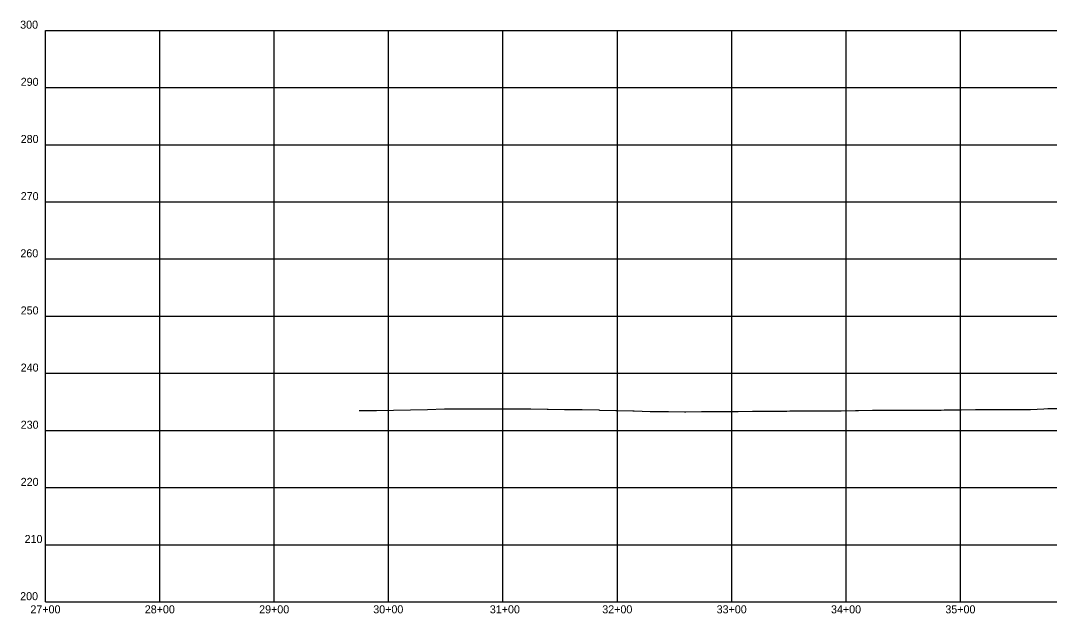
# Model space of a CAD drawing. Extents: x 976639 to 985448, y 1524031 to 1526806.
# Drawn here: x 982604 to 983504, y 1524031 to 1524550 of the extents above; entities that cross this region are included whole.
import ezdxf

# ---------------------------------------------------------------- set-up
doc = ezdxf.new("R2010")
doc.units = 0
for name, color, linetype in [('Default', 7, 'Continuous'), ('R_Axis', 7, 'Continuous'), ('R_Axis Annot', 7, 'Continuous'), ('R_Grid', 7, 'Continuous')]:
    doc.layers.add(name, color=color, linetype=linetype)

msp = doc.modelspace()

# ---------------------------------------------------------------- linework, layer by layer
at = {"layer": 'Default'}
msp.add_lwpolyline([(982900.37, 1524208.73), (982915.54, 1524208.85), (982930.35, 1524209.11), (982945.22, 1524209.57), (982960.19, 1524209.73), (982960.19, 1524209.73), (982960.19, 1524209.73), (982960.23, 1524209.73), (982974.94, 1524210.38), (982975.68, 1524210.39), (982990.12, 1524210.36), (982990.33, 1524210.36), (983000.59, 1524210.4), (983005.17, 1524210.4), (983005.26, 1524210.4), (983020.12, 1524210.4), (983020.15, 1524210.4), (983021.68, 1524210.4), (983035.01, 1524210.31), (983035.34, 1524210.3), (983049.93, 1524210.19), (983050.5, 1524210.18), (983064.85, 1524210.16), (983065.63, 1524210.14), (983080.02, 1524209.8), (983080.33, 1524209.8), (983095.02, 1524209.7), (983095.32, 1524209.69), (983109.87, 1524209.31), (983110.62, 1524209.3), (983124.88, 1524209.01), (983125.58, 1524209), (983139.79, 1524208.61), (983140.76, 1524208.6), (983154.91, 1524208.01), (983155.54, 1524208.01), (983169.77, 1524207.9), (983170.82, 1524207.9), (983184.76, 1524207.75), (983186.08, 1524207.75), (983199.67, 1524207.89), (983201.25, 1524207.88), (983214.53, 1524207.96), (983216.53, 1524207.94), (983229.44, 1524208.03), (983231.7, 1524208.01), (983244.43, 1524208.23), (983246.72, 1524208.22), (983259.4, 1524208.28), (983261.79, 1524208.31), (983274.37, 1524208.4), (983276.85, 1524208.43), (983289.2, 1524208.43), (983292.15, 1524208.48), (983304.3, 1524208.46), (983306.95, 1524208.5), (983319.35, 1524208.69), (983321.89, 1524208.69), (983334.27, 1524208.94), (983337.06, 1524209), (983349.17, 1524209.15), (983352.35, 1524209.17), (983364.07, 1524209.14), (983367.52, 1524209.13), (983379.1, 1524209.15), (983382.46, 1524209.13), (983394.15, 1524209.26), (983397.39, 1524209.29), (983409.35, 1524209.3), (983411.97, 1524209.33), (983424.42, 1524209.46), (983426.87, 1524209.5), (983439.3, 1524209.68), (983442.1, 1524209.77), (983454.06, 1524209.74), (983457.54, 1524209.86), (983469.07, 1524209.62), (983472.52, 1524209.68), (983484.22, 1524209.7), (983487.31, 1524209.73), (983499.1, 1524210.4), (983502.53, 1524210.49), (983514.16, 1524210.75)], dxfattribs=at)
at = {"layer": 'R_Axis'}
for q in [(982626.18, 1524541.42), (985426.18, 1524041.42)]:
    msp.add_line((982626.18, 1524041.42), q, dxfattribs=at)
at = {"layer": 'R_Grid'}
for p, q in [((982626.18, 1524541.42), (985426.18, 1524541.42)), ((982626.18, 1524541.42), (985426.18, 1524541.42)), ((982726.18, 1524041.42), (982726.18, 1524541.42)), ((982826.18, 1524041.42), (982826.18, 1524541.42)), ((982926.18, 1524041.42), (982926.18, 1524541.42)), ((983026.18, 1524041.42), (983026.18, 1524541.42)), ((983126.18, 1524041.42), (983126.18, 1524541.42)), ((983226.18, 1524041.42), (983226.18, 1524541.42)), ((983326.18, 1524041.42), (983326.18, 1524541.42)), ((983426.18, 1524041.42), (983426.18, 1524541.42)), ((982626.18, 1524491.42), (985426.18, 1524491.42)), ((982626.18, 1524441.42), (985426.18, 1524441.42)), ((982626.18, 1524391.42), (985426.18, 1524391.42)), ((982626.18, 1524341.42), (985426.18, 1524341.42)), ((982626.18, 1524291.42), (985426.18, 1524291.42)), ((982626.18, 1524241.42), (985426.18, 1524241.42)), ((982626.18, 1524191.42), (985426.18, 1524191.42)), ((982626.18, 1524141.42), (985426.18, 1524141.42)), ((982626.18, 1524091.42), (985426.18, 1524091.42))]:
    msp.add_line(p, q, dxfattribs=at)

# ---------------------------------------------------------------- texts
at = {"layer": 'R_Axis Annot'}
for s, height, p in [('300', 7, (982604.02, 1524542.92)), ('300', 7, (982604.02, 1524542.92)), ('290', 7, (982604.49, 1524492.92)), ('280', 7, (982604.49, 1524442.92)), ('270', 7, (982604.49, 1524392.92)), ('260', 7, (982604.21, 1524342.92)), ('250', 7, (982604.49, 1524292.92)), ('240', 7, (982604.49, 1524242.92)), ('230', 7, (982604.49, 1524192.92)), ('220', 7, (982604.49, 1524142.92)), ('210', 7, (982607.89, 1524092.92)), ('200', 7, (982604.02, 1524042.92)), ('27+00', 7, (982612.98, 1524031.42)), ('-', 0.0001, (982626.18, 1524041.42)), ('28+00', 7, (982712.98, 1524031.42)), ('29+00', 7, (982812.98, 1524031.42)), ('30+00', 7, (982912.74, 1524031.42)), ('31+00', 7, (983014.68, 1524031.42)), ('32+00', 7, (983112.98, 1524031.42)), ('33+00', 7, (983212.98, 1524031.42)), ('34+00', 7, (983312.98, 1524031.42)), ('35+00', 7, (983412.98, 1524031.42))]:
    msp.add_text(s, height=height, dxfattribs=at).set_placement(p)

doc.saveas('drawing.dxf')
